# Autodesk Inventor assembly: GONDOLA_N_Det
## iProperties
Shininess: 64.0
Length Units: 11272
Angle Units: 11279
Time Units: 11290
Mass Units: 11286
Length Display Precision: 3
Angle Display Precision: 2
Compacted: True
Part Number: GONDOLA_N_Det
Document SubType Name: Assembly
Created: 2005-04
Designer: John Blackburn
Manufacturer: Standard
Standards Organization: Custom
Density: 0.0
Volumn: 0.0
Area: 0.0
PropertySet Name: Model Information
Control State: 0
Master: False
Checked Out: False
Author: John Blackburn
